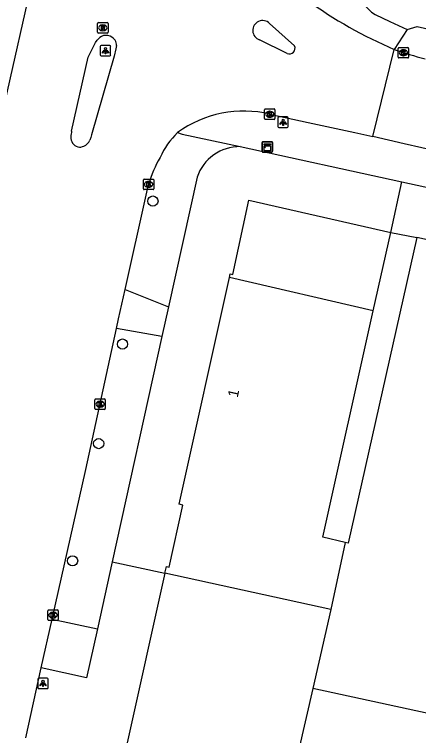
# Model space of a CAD drawing. Extents: x 162172 to 163187, y 382874 to 383684.
# Drawn here: x 162577.3 to 162616.1, y 383101.7 to 383171 of the extents above; entities that cross this region are included whole.
import ezdxf

# ---------------------------------------------------------------- set-up
doc = ezdxf.new("R2010")
doc.units = 0
for name, color, linetype in [('IMGEO_Boom', 7, 'Continuous'), ('IMGEO_Kast', 7, 'Continuous'), ('IMGEO_Kolk', 7, 'Continuous'), ('IMGEO_Lichtpunt', 7, 'Continuous'), ('IMGEO_Pand', 7, 'Continuous'), ('IMGEO_Pand_nummerreeks', 7, 'Continuous'), ('IMGEO_Rijbaan_lokaal_open', 7, 'Continuous'), ('IMGEO_Rioolput', 7, 'Continuous'), ('IMGEO_Voetpad_open', 7, 'Continuous')]:
    doc.layers.add(name, color=color, linetype=linetype)

msp = doc.modelspace()

# ---------------------------------------------------------------- linework, layer by layer
at = {"layer": 'IMGEO_Boom'}
for centre in [(162590.574, 383153.067), (162587.644, 383139.326), (162585.363, 383129.76), (162582.861, 383118.493)]:
    msp.add_circle(centre, 0.489, dxfattribs=at)
at = {"layer": 'IMGEO_Kast'}
for p, q in [((162601.06, 383157.837), (162601.06, 383158.678)), ((162601.06, 383158.678), (162601.06, 383157.837)), ((162601.135, 383158.762), (162601.976, 383158.762)), ((162601.976, 383158.762), (162601.135, 383158.762)), ((162602.06, 383158.687), (162602.06, 383157.846)), ((162602.06, 383157.846), (162602.06, 383158.687)), ((162601.985, 383157.762), (162601.144, 383157.762)), ((162601.144, 383157.762), (162601.985, 383157.762))]:
    msp.add_line(p, q, dxfattribs=at)
for points in [[(162601.255, 383158.552), (162601.855, 383158.552), (162601.855, 383158.467), (162601.255, 383158.467), (162601.255, 383158.552)], [(162601.255, 383158.377), (162601.855, 383158.377), (162601.855, 383157.888), (162601.255, 383157.888), (162601.255, 383158.377)]]:
    msp.add_lwpolyline(points, dxfattribs=at)
msp.add_circle((162601.339, 383158.226), 0.0377, dxfattribs=at)
for centre, start, end in [((162601.138, 383158.684), 92.4484, 184.28452), ((162601.138, 383158.684), 92.4484, 184.28452), ((162601.982, 383158.684), 2.4484, 94.28452), ((162601.982, 383158.684), 2.4484, 94.28452), ((162601.138, 383157.84), 182.4484, 274.28452), ((162601.138, 383157.84), 182.4484, 274.28452), ((162601.982, 383157.84), 272.4484, 4.28452), ((162601.982, 383157.84), 272.4484, 4.28452)]:
    msp.add_arc(centre, 0.0779, start, end, dxfattribs=at)
at = {"layer": 'IMGEO_Kolk'}
for p, q in [((162614.134, 383166.885), (162614.134, 383167.737)), ((162614.209, 383167.811), (162615.061, 383167.811)), ((162614.622, 383167.591), (162614.647, 383167.591)), ((162615.135, 383167.737), (162615.135, 383166.885)), ((162614.645, 383167.031), (162614.62, 383167.031)), ((162615.061, 383166.811), (162614.209, 383166.811)), ((162601.292, 383160.984), (162601.292, 383161.836)), ((162601.367, 383161.91), (162602.219, 383161.91)), ((162601.78, 383161.69), (162601.805, 383161.69)), ((162602.293, 383161.836), (162602.293, 383160.984)), ((162602.219, 383160.91), (162601.367, 383160.91)), ((162601.803, 383161.13), (162601.778, 383161.13)), ((162589.66, 383154.239), (162589.66, 383155.091)), ((162589.735, 383155.165), (162590.587, 383155.165)), ((162590.661, 383155.091), (162590.661, 383154.239)), ((162590.171, 383154.385), (162590.146, 383154.385)), ((162590.148, 383154.945), (162590.173, 383154.945)), ((162590.587, 383154.165), (162589.735, 383154.165)), ((162584.993, 383133.125), (162584.993, 383133.977)), ((162585.068, 383134.051), (162585.92, 383134.051)), ((162585.481, 383133.831), (162585.506, 383133.831)), ((162585.994, 383133.977), (162585.994, 383133.125)), ((162585.92, 383133.051), (162585.068, 383133.051)), ((162585.504, 383133.271), (162585.479, 383133.271)), ((162580.477, 383112.854), (162580.477, 383113.706)), ((162580.552, 383113.78), (162581.404, 383113.78)), ((162580.965, 383113.56), (162580.99, 383113.56)), ((162581.478, 383113.706), (162581.478, 383112.854)), ((162580.988, 383113), (162580.963, 383113)), ((162581.404, 383112.78), (162580.552, 383112.78))]:
    msp.add_line(p, q, dxfattribs=at)
for points in [[(162614.134, 383166.885), (162614.134, 383167.737)], [(162614.209, 383167.811), (162615.061, 383167.811)], [(162615.135, 383167.737), (162615.135, 383166.885)], [(162614.455, 383167.511), (162614.578, 383167.511), (162614.578, 383167.36), (162614.708, 383167.511), (162614.872, 383167.511), (162614.726, 383167.36), (162614.879, 383167.111), (162614.727, 383167.111), (162614.642, 383167.275), (162614.578, 383167.208), (162614.578, 383167.111), (162614.455, 383167.111), (162614.455, 383167.511)], [(162615.061, 383166.811), (162614.209, 383166.811)], [(162601.292, 383160.984), (162601.292, 383161.836)], [(162601.367, 383161.91), (162602.219, 383161.91)], [(162601.613, 383161.61), (162601.736, 383161.61), (162601.736, 383161.459), (162601.866, 383161.61), (162602.03, 383161.61), (162601.884, 383161.459), (162602.037, 383161.21), (162601.885, 383161.21), (162601.8, 383161.374), (162601.736, 383161.307), (162601.736, 383161.21), (162601.613, 383161.21), (162601.613, 383161.61)], [(162602.293, 383161.836), (162602.293, 383160.984)], [(162602.219, 383160.91), (162601.367, 383160.91)], [(162589.66, 383154.239), (162589.66, 383155.091)], [(162589.735, 383155.165), (162590.587, 383155.165)], [(162590.661, 383155.091), (162590.661, 383154.239)], [(162589.981, 383154.865), (162590.104, 383154.865), (162590.104, 383154.714), (162590.234, 383154.865), (162590.398, 383154.865), (162590.252, 383154.714), (162590.405, 383154.465), (162590.253, 383154.465), (162590.168, 383154.629), (162590.104, 383154.562), (162590.104, 383154.465), (162589.981, 383154.465), (162589.981, 383154.865)], [(162590.587, 383154.165), (162589.735, 383154.165)], [(162584.993, 383133.125), (162584.993, 383133.977)], [(162585.068, 383134.051), (162585.92, 383134.051)], [(162585.314, 383133.751), (162585.437, 383133.751), (162585.437, 383133.6), (162585.567, 383133.751), (162585.731, 383133.751), (162585.585, 383133.6), (162585.738, 383133.351), (162585.586, 383133.351), (162585.501, 383133.515), (162585.437, 383133.448), (162585.437, 383133.351), (162585.314, 383133.351), (162585.314, 383133.751)], [(162585.994, 383133.977), (162585.994, 383133.125)], [(162585.92, 383133.051), (162585.068, 383133.051)], [(162580.477, 383112.854), (162580.477, 383113.706)], [(162580.552, 383113.78), (162581.404, 383113.78)], [(162581.478, 383113.706), (162581.478, 383112.854)], [(162580.798, 383113.48), (162580.921, 383113.48), (162580.921, 383113.329), (162581.051, 383113.48), (162581.215, 383113.48), (162581.069, 383113.329), (162581.222, 383113.08), (162581.07, 383113.08), (162580.985, 383113.244), (162580.921, 383113.177), (162580.921, 383113.08), (162580.798, 383113.08), (162580.798, 383113.48)], [(162581.404, 383112.78), (162580.552, 383112.78)]]:
    msp.add_lwpolyline(points, dxfattribs=at)
for centre, start, end in [((162614.211, 383167.735), 91.55205, 178.44795), ((162614.211, 383167.735), 91.55205, 178.44795), ((162615.059, 383167.735), 1.55205, 88.44795), ((162615.059, 383167.735), 1.55205, 88.44795), ((162614.211, 383166.887), 181.55205, 268.44795), ((162614.211, 383166.887), 181.55205, 268.44795), ((162615.059, 383166.887), 271.55205, 358.44795), ((162615.059, 383166.887), 271.55205, 358.44795), ((162601.369, 383161.834), 91.55205, 178.44795), ((162601.369, 383161.834), 91.55205, 178.44795), ((162602.217, 383161.834), 1.55205, 88.44795), ((162602.217, 383161.834), 1.55205, 88.44795), ((162601.369, 383160.986), 181.55205, 268.44795), ((162601.369, 383160.986), 181.55205, 268.44795), ((162602.217, 383160.986), 271.55205, 358.44795), ((162602.217, 383160.986), 271.55205, 358.44795), ((162589.737, 383155.089), 91.55205, 178.44795), ((162589.737, 383155.089), 91.55205, 178.44795), ((162590.585, 383155.089), 1.55205, 88.44795), ((162590.585, 383155.089), 1.55205, 88.44795), ((162589.737, 383154.241), 181.55205, 268.44795), ((162589.737, 383154.241), 181.55205, 268.44795), ((162590.585, 383154.241), 271.55205, 358.44795), ((162590.585, 383154.241), 271.55205, 358.44795), ((162585.07, 383133.975), 91.55205, 178.44795), ((162585.07, 383133.975), 91.55205, 178.44795), ((162585.918, 383133.975), 1.55205, 88.44795), ((162585.918, 383133.975), 1.55205, 88.44795), ((162585.07, 383133.127), 181.55205, 268.44795), ((162585.07, 383133.127), 181.55205, 268.44795), ((162585.918, 383133.127), 271.55205, 358.44795), ((162585.918, 383133.127), 271.55205, 358.44795), ((162580.554, 383113.704), 91.55205, 178.44795), ((162580.554, 383113.704), 91.55205, 178.44795), ((162581.402, 383113.704), 1.55205, 88.44795), ((162581.402, 383113.704), 1.55205, 88.44795), ((162580.554, 383112.856), 181.55205, 268.44795), ((162580.554, 383112.856), 181.55205, 268.44795), ((162581.402, 383112.856), 271.55205, 358.44795), ((162581.402, 383112.856), 271.55205, 358.44795)]:
    msp.add_arc(centre, 0.0765, start, end, dxfattribs=at)
for centre, major_axis, ratio, start_param, end_param in [((162614.621, 383167.311), (-0.387, 0.002), 0.722429, 4.712389, 7.853982), ((162614.646, 383167.311), (-0.39, 0.002), 0.717154, 1.570796, 4.712389), ((162601.779, 383161.41), (-0.387, 0.002), 0.722429, 4.712389, 7.853982), ((162601.804, 383161.41), (-0.39, 0.002), 0.717154, 1.570796, 4.712389), ((162590.147, 383154.665), (-0.387, 0.002), 0.722429, 4.712389, 7.853982), ((162590.172, 383154.665), (-0.39, 0.002), 0.717154, 1.570796, 4.712389), ((162585.48, 383133.551), (-0.387, 0.002), 0.722429, 4.712389, 7.853982), ((162585.505, 383133.551), (-0.39, 0.002), 0.717154, 1.570796, 4.712389), ((162580.964, 383113.28), (-0.387, 0.002), 0.722429, 4.712389, 7.853982), ((162580.989, 383113.28), (-0.39, 0.002), 0.717154, 1.570796, 4.712389)]:
    msp.add_ellipse(centre, major_axis=major_axis, ratio=ratio, start_param=start_param, end_param=end_param, dxfattribs=at)
at = {"layer": 'IMGEO_Lichtpunt'}
for p, q in [((162585.518, 383167.909), (162585.518, 383167.102)), ((162585.518, 383167.909), (162585.518, 383167.102)), ((162586.42, 383168.004), (162585.612, 383168.004)), ((162586.42, 383168.004), (162585.612, 383168.004)), ((162586.514, 383167.102), (162586.514, 383167.909)), ((162586.514, 383167.102), (162586.514, 383167.909)), ((162585.612, 383167.008), (162586.42, 383167.008)), ((162585.612, 383167.008), (162586.42, 383167.008)), ((162602.578, 383161.046), (162602.578, 383160.239)), ((162602.578, 383161.046), (162602.578, 383160.239)), ((162603.48, 383161.141), (162602.672, 383161.141)), ((162603.48, 383161.141), (162602.672, 383161.141)), ((162603.574, 383160.239), (162603.574, 383161.046)), ((162603.574, 383160.239), (162603.574, 383161.046)), ((162602.672, 383160.145), (162603.48, 383160.145)), ((162602.672, 383160.145), (162603.48, 383160.145)), ((162579.517, 383107.123), (162579.517, 383106.316)), ((162579.517, 383107.123), (162579.517, 383106.316)), ((162580.419, 383107.218), (162579.611, 383107.218)), ((162580.419, 383107.218), (162579.611, 383107.218)), ((162580.513, 383106.316), (162580.513, 383107.123)), ((162580.513, 383106.316), (162580.513, 383107.123)), ((162579.611, 383106.222), (162580.419, 383106.222)), ((162579.611, 383106.222), (162580.419, 383106.222))]:
    msp.add_line(p, q, dxfattribs=at)
for points in [[(162585.892, 383167.573), (162585.931, 383167.545), (162585.743, 383167.283), (162585.705, 383167.31), (162585.892, 383167.573)], [(162586.104, 383167.545), (162586.142, 383167.572), (162586.329, 383167.31), (162586.29, 383167.282), (162586.104, 383167.545)], [(162585.994, 383167.525), (162586.041, 383167.525), (162586.041, 383167.203), (162585.994, 383167.203), (162585.994, 383167.525)], [(162602.952, 383160.71), (162602.991, 383160.682), (162602.803, 383160.42), (162602.765, 383160.447), (162602.952, 383160.71)], [(162603.054, 383160.662), (162603.101, 383160.662), (162603.101, 383160.34), (162603.054, 383160.34), (162603.054, 383160.662)], [(162603.164, 383160.682), (162603.202, 383160.709), (162603.389, 383160.447), (162603.35, 383160.419), (162603.164, 383160.682)], [(162579.891, 383106.787), (162579.93, 383106.759), (162579.742, 383106.497), (162579.704, 383106.524), (162579.891, 383106.787)], [(162579.993, 383106.739), (162580.04, 383106.739), (162580.04, 383106.417), (162579.993, 383106.417), (162579.993, 383106.739)], [(162580.103, 383106.759), (162580.141, 383106.786), (162580.328, 383106.524), (162580.289, 383106.496), (162580.103, 383106.759)]]:
    msp.add_lwpolyline(points, dxfattribs=at)
for centre in [(162586.017, 383167.707), (162603.077, 383160.844), (162580.016, 383106.921)]:
    msp.add_circle(centre, 0.0994, dxfattribs=at)
for centre, start, end in [((162585.612, 383167.909), 90, 180), ((162585.612, 383167.909), 90, 180), ((162586.42, 383167.909), 0, 90), ((162586.42, 383167.909), 0, 90), ((162585.612, 383167.102), 180, 270), ((162585.612, 383167.102), 180, 270), ((162586.42, 383167.102), 270, 0), ((162586.42, 383167.102), 270, 360), ((162602.672, 383161.046), 90, 180), ((162602.672, 383161.046), 90, 180), ((162603.48, 383161.046), 0, 90), ((162603.48, 383161.046), 0, 90), ((162602.672, 383160.239), 180, 270), ((162602.672, 383160.239), 180, 270), ((162603.48, 383160.239), 270, 0), ((162603.48, 383160.239), 270, 360), ((162579.611, 383107.123), 90, 180), ((162579.611, 383107.123), 90, 180), ((162580.419, 383107.123), 0, 90), ((162580.419, 383107.123), 0, 90), ((162579.611, 383106.316), 180, 270), ((162579.611, 383106.316), 180, 270), ((162580.419, 383106.316), 270, 0), ((162580.419, 383106.316), 270, 360)]:
    msp.add_arc(centre, 0.0946, start, end, dxfattribs=at)
at = {"layer": 'IMGEO_Pand'}
for points in [[(162597.915, 383145.714), (162597.994, 383146.073), (162598.259, 383146.014), (162599.773, 383153.152), (162613.424, 383150.059)], [(162615.917, 383149.56), (162609.336, 383120.209), (162609.038, 383120.276)], [(162611.739, 383142.512), (162613.424, 383150.059)], [(162635.424, 383145.306), (162615.917, 383149.56)], [(162591.717, 383117.299), (162591.863, 383117.959), (162592.128, 383117.901), (162593.446, 383123.854), (162593.094, 383123.932), (162597.915, 383145.714)], [(162611.739, 383142.512), (162597.915, 383145.714)], [(162609.038, 383120.276), (162606.882, 383120.76), (162611.739, 383142.512)], [(162609.038, 383120.276), (162607.662, 383113.818)], [(162591.717, 383117.299), (162588.111, 383101.011)], [(162607.662, 383113.818), (162591.717, 383117.299)], [(162607.662, 383113.818), (162605.924, 383106.249)], [(162627.504, 383109.562), (162625.79, 383101.932), (162625.476, 383102), (162624.255, 383102.266), (162605.924, 383106.249)], [(162605.924, 383106.249), (162603.809, 383097.034), (162588.005, 383100.532)]]:
    msp.add_lwpolyline(points, dxfattribs=at)
at = {"layer": 'IMGEO_Rijbaan_lokaal_open'}
for points in [[(162579.472, 383177.4), (162579.006, 383174.463), (162576.34, 383162.62)], [(162601.783, 383170.137), (162604.179, 383167.981)], [(162582.757, 383159.778), (162584.352, 383166.878), (162585.045, 383168.3), (162585.211, 383168.538), (162585.458, 383168.786)], [(162603.474, 383167.237), (162600.811, 383168.554)], [(162587.074, 383168.02), (162587.011, 383167.684), (162586.841, 383166.974)], [(162611.71, 383159.259), (162613.76, 383167.637)], [(162586.841, 383166.974), (162584.683, 383159.416), (162584.605, 383159.161), (162584.508, 383158.916)], [(162601.819, 383161.405), (162605.5, 383160.618), (162609.97, 383159.656), (162611.71, 383159.259)], [(162637.042, 383153.547), (162630.442, 383155.04), (162623.509, 383156.587), (162619.796, 383157.416), (162614.715, 383158.574), (162611.71, 383159.259)], [(162587.893, 383144.553), (162589.934, 383153.632), (162590.161, 383154.67)], [(162587.061, 383140.816), (162587.264, 383141.755), (162587.893, 383144.553)], [(162580.892, 383112.905), (162584.135, 383127.261), (162587.061, 383140.816)], [(162579.85, 383108.231), (162580.892, 383112.905)], [(162578.357, 383101.491), (162579.85, 383108.231)]]:
    msp.add_lwpolyline(points, dxfattribs=at)
for centre, radius, start, end in [((162630.08, 383206.193), 41.867, 233.81256, 247.05826), ((162601.118, 383169.455), 0.952, 45.70839, 251.18976), ((162586.066, 383167.943), 1.039, 33.46698, 125.78662), ((162586.306, 383168.07), 0.769, 356.28914, 35.44902), ((162603.668, 383167.759), 0.557, 249.65079, 23.43271), ((162624.884, 383198.452), 32.762, 250.15119, 255.55054), ((162599.273, 383151.005), 10.707, 76.24199, 126.23881), ((162583.639, 383159.178), 0.95, 176.0617, 253.24912), ((162589.564, 383158.667), 6.897, 170.72752, 175.20702), ((162598.521, 383153.911), 7.997, 134.22746, 155.29403), ((162583.505, 383159.343), 1.09, 294.16031, 336.9601), ((162583.543, 383159.148), 0.898, 258.54085, 297.00693), ((162603.038, 383150.735), 13.465, 151.04666, 163.00667)]:
    msp.add_arc(centre, radius, start, end, dxfattribs=at)
at = {"layer": 'IMGEO_Rioolput'}
for p, q in [((162585.261, 383169.282), (162585.261, 383170.134)), ((162585.336, 383170.208), (162586.188, 383170.208)), ((162585.749, 383169.988), (162585.774, 383169.988)), ((162586.262, 383170.134), (162586.262, 383169.282)), ((162586.188, 383169.208), (162585.336, 383169.208)), ((162585.772, 383169.428), (162585.747, 383169.428))]:
    msp.add_line(p, q, dxfattribs=at)
for points in [[(162585.261, 383169.282), (162585.261, 383170.134)], [(162585.336, 383170.208), (162586.188, 383170.208)], [(162585.85, 383169.906), (162585.598, 383169.908), (162585.598, 383169.508)], [(162585.598, 383169.508), (162585.722, 383169.508), (162585.722, 383169.67), (162585.733, 383169.67)], [(162585.776, 383169.827), (162585.722, 383169.827), (162585.722, 383169.746)], [(162585.722, 383169.746), (162585.774, 383169.746)], [(162585.78, 383169.641), (162585.851, 383169.508), (162585.991, 383169.508), (162585.926, 383169.634)], [(162586.262, 383170.134), (162586.262, 383169.282)], [(162586.188, 383169.208), (162585.336, 383169.208)]]:
    msp.add_lwpolyline(points, dxfattribs=at)
for centre, radius, start, end in [((162585.338, 383170.132), 0.0765, 91.55205, 178.44795), ((162585.338, 383170.132), 0.0765, 91.55205, 178.44795), ((162585.732, 383169.617), 0.0533, 26.02933, 88.69889), ((162585.758, 383169.935), 0.19, 274.7715, 282.96867), ((162585.782, 383169.731), 0.0964, 77.00612, 93.18647), ((162585.796, 383169.788), 0.0378, 276.66336, 79.67722), ((162585.849, 383169.796), 0.109, 350.36119, 89.41601), ((162585.847, 383169.796), 0.112, 277.58423, 350.98172), ((162585.831, 383169.581), 0.108, 29.51342, 73.79051), ((162586.186, 383170.132), 0.0765, 1.55205, 88.44795), ((162586.186, 383170.132), 0.0765, 1.55205, 88.44795), ((162585.338, 383169.284), 0.0765, 181.55205, 268.44795), ((162585.338, 383169.284), 0.0765, 181.55205, 268.44795), ((162586.186, 383169.284), 0.0765, 271.55205, 358.44795), ((162586.186, 383169.284), 0.0765, 271.55205, 358.44795)]:
    msp.add_arc(centre, radius, start, end, dxfattribs=at)
for centre, major_axis, ratio, start_param, end_param in [((162585.748, 383169.708), (-0.387, 0.002), 0.722429, 4.712389, 7.853982), ((162585.773, 383169.708), (-0.39, 0.002), 0.717154, 1.570796, 4.712389)]:
    msp.add_ellipse(centre, major_axis=major_axis, ratio=ratio, start_param=start_param, end_param=end_param, dxfattribs=at)
at = {"layer": 'IMGEO_Voetpad_open'}
for points in [[(162611.927, 383170.996), (162613.319, 383170.332), (162615.003, 383169.56)], [(162615.003, 383169.56), (162615.953, 383169.851), (162618.069, 383169.371)], [(162615.003, 383169.56), (162613.76, 383167.637)], [(162592.943, 383159.641), (162593.371, 383159.494), (162598.969, 383158.296)], [(162598.969, 383158.296), (162614.482, 383154.918)], [(162594.812, 383155.347), (162592.06, 383142.889)], [(162613.424, 383150.059), (162614.482, 383154.918)], [(162614.482, 383154.918), (162636.279, 383150.172)], [(162613.424, 383150.059), (162615.917, 383149.56)], [(162587.893, 383144.553), (162592.06, 383142.889)], [(162592.06, 383142.889), (162591.437, 383140.064)], [(162591.437, 383140.064), (162587.061, 383140.816)], [(162591.437, 383140.064), (162586.656, 383118.417)], [(162586.656, 383118.417), (162585.234, 383111.98)], [(162586.656, 383118.417), (162591.717, 383117.299)], [(162580.892, 383112.905), (162585.234, 383111.98)], [(162585.234, 383111.98), (162584.187, 383107.254), (162579.85, 383108.231)]]:
    msp.add_lwpolyline(points, dxfattribs=at)
for centre, radius, start, end in [((162613.686, 383174.026), 3.503, 132.44034, 239.85912), ((162598.915, 383153.968), 4.328, 89.28074, 161.42348)]:
    msp.add_arc(centre, radius, start, end, dxfattribs=at)

# ---------------------------------------------------------------- texts
at = {"layer": 'IMGEO_Pand_nummerreeks'}
msp.add_text('1', height=1, rotation=77.52107, dxfattribs=at).set_placement((162598.712, 383134.137))

doc.saveas('drawing.dxf')
